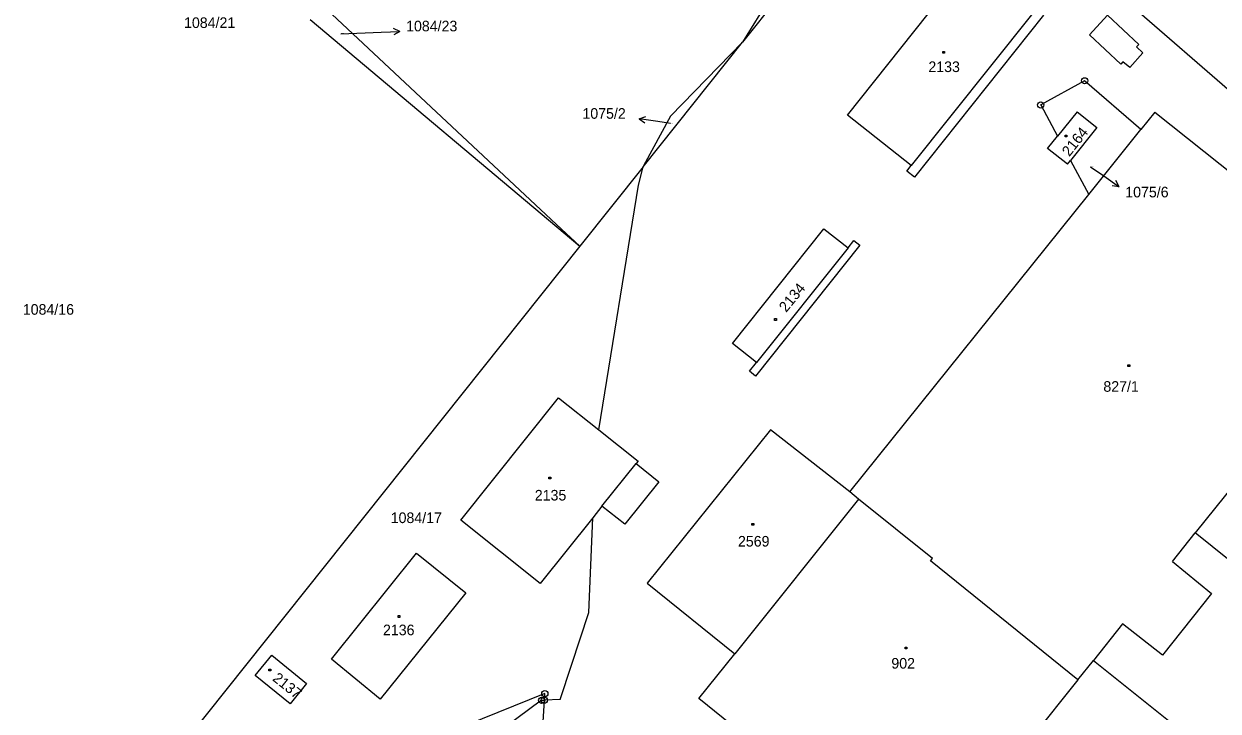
# Model space of a CAD drawing. Extents: x -795483 to -789093, y -1112258 to -1108741.
# Drawn here: x -792517.6 to -792326, y -1109465.3 to -1109355.1 of the extents above; entities that cross this region are included whole.
import ezdxf

# ---------------------------------------------------------------- set-up
doc = ezdxf.new("R2010")
doc.units = 0
for name, color, linetype in [('Komunikace', 7, 'Continuous'), ('Vrstva 1', 7, 'Continuous'), ('Vrstva 14', 7, 'Continuous'), ('Vrstva 15', 7, 'Continuous'), ('Vrstva 16', 7, 'Continuous'), ('Vrstva 2', 7, 'Continuous'), ('Vrstva 25', 7, 'Continuous'), ('Vrstva 28', 7, 'Continuous')]:
    doc.layers.add(name, color=color, linetype=linetype)

msp = doc.modelspace()

# ---------------------------------------------------------------- linework, layer by layer
at = {"layer": 'Komunikace'}
for p, q in [((-792466.79, -1109356.68), (-792460.3, -1109356.41)), ((-792413.89, -1109371.08), (-792415.92, -1109370.77)), ((-792346.46, -1109378), (-792344.36, -1109379.49))]:
    msp.add_line(p, q, dxfattribs=at)
at = {"layer": 'Vrstva 1'}
for p, q in [((-792382.01, -1109332.59), (-792402.35, -1109358)), ((-792385.48, -1109369.75), (-792366.15, -1109345.46)), ((-792397.33, -1109349.96), (-792402.35, -1109358)), ((-792272.12, -1109411.1), (-792343.43, -1109349.12)), ((-792469.9, -1109352.01), (-792431.35, -1109388)), ((-792354.04, -1109353.67), (-792374.75, -1109379.66)), ((-792471.69, -1109354.38), (-792428.41, -1109390.74)), ((-792418.28, -1109378.04), (-792402.35, -1109358)), ((-792402.35, -1109358), (-792413.85, -1109369.89)), ((-792347.44, -1109364.22), (-792354.48, -1109368.09)), ((-792338.4, -1109372.06), (-792347.44, -1109364.22)), ((-792354.48, -1109368.09), (-792351.8, -1109373.1)), ((-792348.63, -1109369.22), (-792351.8, -1109373.1)), ((-792348.63, -1109369.22), (-792345.46, -1109371.7)), ((-792336.14, -1109369.25), (-792338.4, -1109372.06)), ((-792336.14, -1109369.25), (-792323.08, -1109379.69)), ((-792413.85, -1109369.89), (-792418.23, -1109377.84)), ((-792375.26, -1109377.83), (-792385.48, -1109369.75)), ((-792353.41, -1109375.07), (-792351.8, -1109373.1)), ((-792345.46, -1109371.7), (-792349.71, -1109376.99)), ((-792346.77, -1109382.48), (-792338.4, -1109372.06)), ((-792350.19, -1109377.59), (-792353.41, -1109375.07)), ((-792350.19, -1109377.59), (-792349.71, -1109376.99)), ((-792349.71, -1109376.99), (-792346.77, -1109382.48)), ((-792418.28, -1109378.04), (-792428.41, -1109390.74)), ((-792419.02, -1109380.95), (-792418.28, -1109378.04)), ((-792418.23, -1109377.84), (-792418.28, -1109378.04)), ((-792375.96, -1109378.73), (-792375.26, -1109377.83)), ((-792374.75, -1109379.66), (-792375.96, -1109378.73)), ((-792425.38, -1109420.2), (-792419.02, -1109380.95)), ((-792385.1, -1109430.16), (-792346.77, -1109382.48)), ((-792431.35, -1109388), (-792428.41, -1109390.74)), ((-792403.93, -1109406.34), (-792389.26, -1109387.97)), ((-792389.26, -1109387.97), (-792385.39, -1109391.04)), ((-792383.51, -1109390.59), (-792400.26, -1109411.58)), ((-792385.39, -1109391.04), (-792384.46, -1109389.83)), ((-792384.46, -1109389.83), (-792383.51, -1109390.59)), ((-792428.41, -1109390.74), (-792510.08, -1109493.1)), ((-792400.1, -1109409.41), (-792403.93, -1109406.34)), ((-792401.22, -1109410.8), (-792400.1, -1109409.41)), ((-792306.77, -1109408.1), (-792329.67, -1109436.74)), ((-792400.26, -1109411.58), (-792401.22, -1109410.8)), ((-792447.54, -1109434.68), (-792431.83, -1109415.06)), ((-792431.83, -1109415.06), (-792425.38, -1109420.2)), ((-792425.38, -1109420.2), (-792419.09, -1109425.22)), ((-792397.84, -1109420.2), (-792417.64, -1109444.78)), ((-792385.1, -1109430.16), (-792397.84, -1109420.2)), ((-792419.09, -1109425.22), (-792419.41, -1109425.62)), ((-792419.41, -1109425.62), (-792415.76, -1109428.55)), ((-792415.76, -1109428.55), (-792421.21, -1109435.32)), ((-792383.7, -1109431.34), (-792385.1, -1109430.16)), ((-792424.89, -1109432.47), (-792426.36, -1109434.31)), ((-792421.21, -1109435.32), (-792424.89, -1109432.47)), ((-792383.7, -1109431.34), (-792403.53, -1109456.13)), ((-792371.84, -1109440.84), (-792383.7, -1109431.34)), ((-792426.36, -1109434.31), (-792434.8, -1109444.85)), ((-792427, -1109449.48), (-792426.36, -1109434.31)), ((-792434.8, -1109444.85), (-792447.54, -1109434.68)), ((-792333.34, -1109441.33), (-792329.67, -1109436.74)), ((-792324.22, -1109441.09), (-792329.67, -1109436.74)), ((-792468.29, -1109457.01), (-792454.61, -1109440)), ((-792454.61, -1109440), (-792446.74, -1109446.35)), ((-792372.15, -1109441.24), (-792371.84, -1109440.84)), ((-792348.5, -1109460.3), (-792372.15, -1109441.24)), ((-792333.34, -1109441.33), (-792327.06, -1109446.44)), ((-792417.64, -1109444.78), (-792403.53, -1109456.13)), ((-792446.74, -1109446.35), (-792460.46, -1109463.4)), ((-792327.06, -1109446.44), (-792334.95, -1109456.33)), ((-792429.77, -1109457.94), (-792427, -1109449.48)), ((-792341.33, -1109451.32), (-792346.01, -1109457.18)), ((-792334.95, -1109456.33), (-792341.33, -1109451.32)), ((-792480.5, -1109459.61), (-792477.86, -1109456.36)), ((-792477.86, -1109456.36), (-792472.27, -1109460.89)), ((-792460.46, -1109463.4), (-792468.29, -1109457.01)), ((-792409.35, -1109463.3), (-792403.53, -1109456.13)), ((-792348.5, -1109460.3), (-792346.01, -1109457.18)), ((-792346.01, -1109457.18), (-792328.15, -1109471.45)), ((-792431.57, -1109463.44), (-792429.77, -1109457.94)), ((-792474.92, -1109464.14), (-792480.5, -1109459.61)), ((-792472.27, -1109460.89), (-792474.92, -1109464.14)), ((-792348.5, -1109460.3), (-792367.44, -1109483.92)), ((-792434.04, -1109462.51), (-792477.32, -1109479.92)), ((-792434.11, -1109463.56), (-792434.04, -1109462.51)), ((-792391.29, -1109477.75), (-792409.35, -1109463.3)), ((-792434.56, -1109463.58), (-792440.38, -1109467.87)), ((-792434.65, -1109472.18), (-792434.11, -1109463.56)), ((-792434.56, -1109463.58), (-792434.11, -1109463.56)), ((-792431.57, -1109463.44), (-792434.11, -1109463.56))]:
    msp.add_line(p, q, dxfattribs=at)
at = {"layer": 'Vrstva 16'}
for p, q in [((-792457.3, -1109356.29), (-792458.32, -1109355.83)), ((-792460.3, -1109356.41), (-792457.3, -1109356.29)), ((-792457.3, -1109356.29), (-792458.28, -1109356.83)), ((-792418.88, -1109370.31), (-792417.82, -1109369.97)), ((-792415.92, -1109370.77), (-792418.88, -1109370.31)), ((-792418.88, -1109370.31), (-792417.97, -1109370.96)), ((-792344.36, -1109379.49), (-792341.91, -1109381.22)), ((-792341.91, -1109381.22), (-792342.44, -1109380.24)), ((-792341.91, -1109381.22), (-792343.02, -1109381.05))]:
    msp.add_line(p, q, dxfattribs=at)
at = {"layer": 'Vrstva 2'}
for p, q in [((-792355.93, -1109353.62), (-792375.26, -1109377.83)), ((-792346.63, -1109356.84), (-792343.78, -1109353.71)), ((-792343.78, -1109353.71), (-792338.74, -1109358.38)), ((-792341.61, -1109361.53), (-792346.63, -1109356.84)), ((-792338.09, -1109359.72), (-792340.2, -1109362.1)), ((-792338.74, -1109358.38), (-792339.11, -1109358.8)), ((-792339.11, -1109358.8), (-792338.09, -1109359.72)), ((-792341.32, -1109361.17), (-792341.61, -1109361.53)), ((-792340.2, -1109362.1), (-792341.32, -1109361.17)), ((-792385.39, -1109391.04), (-792400.1, -1109409.41)), ((-792424.89, -1109432.47), (-792419.41, -1109425.62))]:
    msp.add_line(p, q, dxfattribs=at)
at = {"layer": 'Vrstva 25'}
for p, q in [((-792370.2, -1109359.51), (-792369.9, -1109359.51)), ((-792370.2, -1109359.81), (-792370.2, -1109359.51)), ((-792369.9, -1109359.81), (-792370.2, -1109359.81)), ((-792369.9, -1109359.51), (-792369.9, -1109359.81)), ((-792350.57, -1109372.93), (-792350.27, -1109372.93)), ((-792350.57, -1109373.23), (-792350.57, -1109372.93)), ((-792350.27, -1109373.23), (-792350.57, -1109373.23)), ((-792350.27, -1109372.93), (-792350.27, -1109373.23)), ((-792397.19, -1109402.35), (-792396.89, -1109402.35)), ((-792397.19, -1109402.65), (-792397.19, -1109402.35)), ((-792396.89, -1109402.65), (-792397.19, -1109402.65)), ((-792396.89, -1109402.35), (-792396.89, -1109402.65)), ((-792340.47, -1109409.76), (-792340.17, -1109409.76)), ((-792340.47, -1109410.06), (-792340.47, -1109409.76)), ((-792340.17, -1109409.76), (-792340.17, -1109410.06)), ((-792340.17, -1109410.06), (-792340.47, -1109410.06)), ((-792433.4, -1109427.79), (-792433.1, -1109427.79)), ((-792433.4, -1109428.09), (-792433.4, -1109427.79)), ((-792433.1, -1109428.09), (-792433.4, -1109428.09)), ((-792433.1, -1109427.79), (-792433.1, -1109428.09)), ((-792400.8, -1109435.21), (-792400.5, -1109435.21)), ((-792400.8, -1109435.51), (-792400.8, -1109435.21)), ((-792400.5, -1109435.51), (-792400.8, -1109435.51)), ((-792400.5, -1109435.21), (-792400.5, -1109435.51)), ((-792457.59, -1109450.01), (-792457.29, -1109450.01)), ((-792457.59, -1109450.31), (-792457.59, -1109450.01)), ((-792457.29, -1109450.31), (-792457.59, -1109450.31)), ((-792457.29, -1109450.01), (-792457.29, -1109450.31)), ((-792376.23, -1109455.05), (-792375.93, -1109455.05)), ((-792376.23, -1109455.35), (-792376.23, -1109455.05)), ((-792375.93, -1109455.35), (-792376.23, -1109455.35)), ((-792375.93, -1109455.05), (-792375.93, -1109455.35)), ((-792478.31, -1109458.57), (-792478.01, -1109458.57)), ((-792478.31, -1109458.87), (-792478.31, -1109458.57)), ((-792478.01, -1109458.87), (-792478.31, -1109458.87)), ((-792478.01, -1109458.57), (-792478.01, -1109458.87))]:
    msp.add_line(p, q, dxfattribs=at)
at = {"layer": 'Vrstva 28'}
for centre, radius in [((-792347.44, -1109364.22), 0.5), ((-792347.44, -1109364.22), 0.01), ((-792354.48, -1109368.09), 0.5), ((-792354.48, -1109368.09), 0.01), ((-792434.56, -1109463.58), 0.5), ((-792434.11, -1109463.56), 0.5), ((-792434.04, -1109462.51), 0.5), ((-792434.04, -1109462.51), 0.01), ((-792434.56, -1109463.58), 0.01), ((-792434.11, -1109463.56), 0.01)]:
    msp.add_circle(centre, radius, dxfattribs=at)

# ---------------------------------------------------------------- texts
at = {"layer": 'Vrstva 14'}
for s, height, p in [('1084/23', 0.1, (-792466.79, -1109356.68)), ('1075/2', 0.1, (-792413.89, -1109371.08)), ('1075/6', 0.1, (-792346.46, -1109378)), ('1084/16', 1.7, (-792517.8, -1109401.74)), ('1084/17', 1.7, (-792458.77, -1109435.16))]:
    msp.add_text(s, height=height, dxfattribs=at).set_placement(p)
at = {"layer": 'Vrstva 15'}
for s, p in [('2133', (-792372.5, -1109362.82)), ('827/1', (-792344.42, -1109414.1)), ('2135', (-792435.65, -1109431.54)), ('2569', (-792403.05, -1109438.93)), ('2136', (-792460.01, -1109453.15)), ('902', (-792378.44, -1109458.5))]:
    msp.add_text(s, height=1.7, dxfattribs=at).set_placement(p)
for s, rotation, p in [('2164', 51.5268, (-792349.89, -1109376.48)), ('2134', 50.7474, (-792395.31, -1109401.46)), ('2137', 321.1947, (-792477.86, -1109460.3))]:
    msp.add_text(s, height=1.7, rotation=rotation, dxfattribs=at).set_placement(p)
at = {"layer": 'Vrstva 16'}
for s, p in [('1084/21', (-792491.93, -1109355.75)), ('1084/23', (-792456.3, -1109356.29)), ('1075/2', (-792428.01, -1109370.31)), ('1075/6', (-792340.91, -1109382.92))]:
    msp.add_text(s, height=1.7, dxfattribs=at).set_placement(p)

doc.saveas('drawing.dxf')
